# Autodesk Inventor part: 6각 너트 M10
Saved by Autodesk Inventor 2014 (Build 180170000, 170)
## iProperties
Created: 2026-03
Part Number: 6각 너트 M10
Material: 일반
Document SubType Name: Modeling
Designer: dg
Density: 1 g/cm^3
Appearance: 기본값
Author: dg
Author: jhkim
Description: 6각 너트 및 6각 가는 너트
Creation Date: 2025-06-27
Sending System: Autodesk Inventor 2026
Preprocessor: ST-DEVELOPER v20.1
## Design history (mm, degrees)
node "6각 너트 M101"
body "Solid1"
node "기준1"
